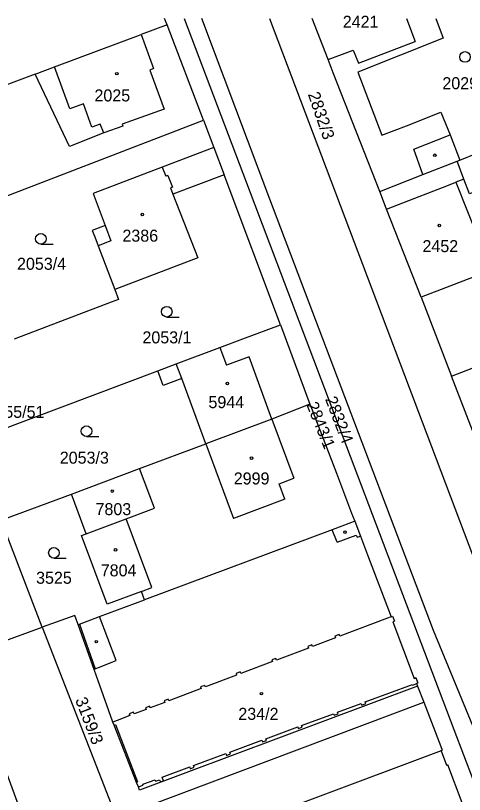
# Model space of a CAD drawing. Extents: x -564952 to -564307, y -1202373 to -1201847.
# Drawn here: x -564730.1 to -564666.6, y -1201959.8 to -1201849.7 of the extents above; entities that cross this region are included whole.
import ezdxf

# ---------------------------------------------------------------- set-up
doc = ezdxf.new("R2010")
doc.units = 0
for name, color, linetype in [('Hranice parcel', 7, 'Continuous'), ('Parcelní čísla', 7, 'Continuous'), ('Vnitřní kresba', 7, 'Continuous'), ('Značky budov', 7, 'Continuous'), ('Značky kultur', 7, 'Continuous')]:
    doc.layers.add(name, color=color, linetype=linetype)

msp = doc.modelspace()

# ---------------------------------------------------------------- linework, layer by layer
at = {"layer": 'Hranice parcel'}
for p, q in [((-564708.7, -1201850.95), (-564709.04, -1201850.07)), ((-564706.28, -1201850.07), (-564668.12, -1201950.64)), ((-564694.16, -1201875.63), (-564703.8, -1201850.07)), ((-564694.18, -1201850.07), (-564686.16, -1201871.23)), ((-564708.7, -1201850.95), (-564712.36, -1201852.32)), ((-564703.52, -1201864.46), (-564708.7, -1201850.95)), ((-564724.64, -1201856.92), (-564712.36, -1201852.32)), ((-564712.36, -1201852.32), (-564710.6, -1201857.14)), ((-564727.38, -1201857.94), (-564724.64, -1201856.92)), ((-564737.23, -1201877.39), (-564703.52, -1201864.46)), ((-564703.52, -1201864.46), (-564702.07, -1201868.33)), ((-564702.07, -1201868.33), (-564709.37, -1201871.11)), ((-564702.07, -1201868.33), (-564700.62, -1201872.17)), ((-564667.27, -1201870.1), (-564664.94, -1201869.19)), ((-564692.64, -1201893.4), (-564700.62, -1201872.17)), ((-564662.87, -1201885.69), (-564672.74, -1201889.5)), ((-564672.74, -1201889.5), (-564668.43, -1201900.65)), ((-564692.64, -1201893.4), (-564688.47, -1201904.65)), ((-564736.45, -1201909.86), (-564710.02, -1201899.92)), ((-564703.22, -1201910.26), (-564706.62, -1201900.99)), ((-564712.58, -1201913.74), (-564703.22, -1201910.26)), ((-564722.24, -1201917.34), (-564712.58, -1201913.74)), ((-564732.16, -1201921.04), (-564722.24, -1201917.34)), ((-564720.15, -1201922.96), (-564722.24, -1201917.34)), ((-564726.36, -1201936.19), (-564732.16, -1201921.04)), ((-564720.15, -1201922.96), (-564714.47, -1201920.84)), ((-564711.89, -1201932.3), (-564712.33, -1201931.11)), ((-564721.74, -1201934.52), (-564726.36, -1201936.19)), ((-564673.25, -1201944.51), (-564672.37, -1201946.79)), ((-564668.12, -1201950.64), (-564653.5, -1201989.14))]:
    msp.add_line(p, q, dxfattribs=at)
for points in [[(-564678.6, -1201874.56), (-564685.18, -1201857.76), (-564685.91, -1201855.87), (-564688.16, -1201850.07)], [(-564670.64, -1201850.07), (-564669.6, -1201852.87), (-564681.68, -1201857.67), (-564678.29, -1201866.56), (-564674.81, -1201865.25), (-564669.96, -1201863.32), (-564668.61, -1201866.52), (-564667.27, -1201870.1)], [(-564710.6, -1201857.14), (-564711.16, -1201857.36), (-564709.11, -1201862.88), (-564715.07, -1201865.02), (-564714.96, -1201865.29), (-564717.67, -1201866.26), (-564722.49, -1201868.17), (-564727.38, -1201857.94)], [(-564727.38, -1201857.94), (-564753.52, -1201867.7), (-564747.75, -1201881.47)], [(-564678.6, -1201874.56), (-564672.48, -1201872.15), (-564667.64, -1201870.24), (-564667.27, -1201870.1)], [(-564709.37, -1201871.11), (-564719.17, -1201874.83), (-564717.48, -1201879.35), (-564719.29, -1201880.05), (-564718.94, -1201880.95), (-564718.45, -1201882.23), (-564716.1, -1201888.41)], [(-564686.16, -1201871.23), (-564677.08, -1201895.29), (-564660.17, -1201939.88), (-564659.23, -1201942.17), (-564652.34, -1201954.8), (-564647.57, -1201960.74), (-564641.3, -1201967.43), (-564636.51, -1201971.74), (-564631.4, -1201974.9), (-564623.41, -1201978.76)], [(-564700.62, -1201872.17), (-564707.88, -1201874.94), (-564704.36, -1201883.94), (-564716.1, -1201888.41)], [(-564663.07, -1201873.83), (-564665.89, -1201874.89), (-564666.68, -1201872.79), (-564667.81, -1201873.23), (-564662.87, -1201885.69)], [(-564672.74, -1201889.5), (-564677.63, -1201877.03), (-564678.6, -1201874.56)], [(-564661.15, -1201960.44), (-564670.99, -1201936.66), (-564694.16, -1201875.63)], [(-564716.1, -1201888.41), (-564715.57, -1201889.81), (-564716.6, -1201890.2), (-564730.34, -1201895.42)], [(-564710.02, -1201899.92), (-564707.39, -1201898.93), (-564701.23, -1201896.62), (-564697.99, -1201895.41), (-564692.64, -1201893.4)], [(-564668.43, -1201900.65), (-564659.44, -1201897.19), (-564656.68, -1201896.09)], [(-564706.62, -1201900.99), (-564709.25, -1201901.97), (-564710.02, -1201899.92)], [(-564661.94, -1201917.34), (-564664.31, -1201911.26), (-564668.43, -1201900.65)], [(-564688.47, -1201904.65), (-564693.85, -1201906.77), (-564703.22, -1201910.26)], [(-564688.47, -1201904.65), (-564688.27, -1201905.18), (-564684.73, -1201914.39)], [(-564714.47, -1201920.84), (-564710.49, -1201919.36), (-564712.58, -1201913.74)], [(-564684.73, -1201914.39), (-564682.57, -1201920.04), (-564682.13, -1201921.2)], [(-564712.33, -1201931.11), (-564710.85, -1201930.56), (-564714.47, -1201920.84)], [(-564682.13, -1201921.2), (-564682.58, -1201921.37), (-564685.33, -1201922.39), (-564711.89, -1201932.3)], [(-564682.13, -1201921.2), (-564681.34, -1201923.29), (-564680.33, -1201925.94), (-564676.99, -1201934.7), (-564676.78, -1201934.62), (-564676.52, -1201935.32), (-564676.76, -1201935.41), (-564673.74, -1201943.42), (-564673.49, -1201943.32), (-564673.2, -1201944.1), (-564673.38, -1201944.17), (-564673.25, -1201944.51)], [(-564712.33, -1201931.11), (-564717.17, -1201932.91), (-564720.79, -1201923.2), (-564720.15, -1201922.96)], [(-564721.28, -1201935.81), (-564721.1, -1201935.74), (-564718.26, -1201934.68), (-564711.89, -1201932.3)], [(-564721.28, -1201935.81), (-564721.55, -1201935.06), (-564721.74, -1201934.52)], [(-564711.3, -1202011.73), (-564714.18, -1202003.86), (-564737.5, -1201940.24), (-564726.36, -1201936.19)], [(-564726.36, -1201936.19), (-564715.86, -1201963.16), (-564672.37, -1201946.79)], [(-564673.25, -1201944.51), (-564712.62, -1201959.24), (-564712.76, -1201958.76), (-564713.05, -1201958.13), (-564716.2, -1201950.04), (-564716.38, -1201949.6), (-564716.43, -1201949.46), (-564721.28, -1201935.81)], [(-564672.37, -1201946.79), (-564669.95, -1201953.07), (-564669.75, -1201953.6), (-564669.89, -1201953.65)], [(-564669.89, -1201953.65), (-564706.41, -1201967.36), (-564714.12, -1201970.26), (-564699.64, -1202009.87)], [(-564669.89, -1201953.65), (-564669.13, -1201955.68), (-564668.99, -1201955.63), (-564666.96, -1201960.96)]]:
    msp.add_lwpolyline(points, dxfattribs=at)
at = {"layer": 'Vnitřní kresba'}
for p, q in [((-564674.82, -1201850.07), (-564673.59, -1201853.3)), ((-564681.62, -1201856.39), (-564673.59, -1201853.3)), ((-564685.91, -1201855.87), (-564682.73, -1201854.69)), ((-564682.73, -1201854.69), (-564682.34, -1201854.54)), ((-564682.34, -1201854.54), (-564681.62, -1201856.39)), ((-564722.45, -1201862.85), (-564724.64, -1201856.92)), ((-564720.54, -1201862.14), (-564722.45, -1201862.85)), ((-564719.33, -1201865.46), (-564720.54, -1201862.14)), ((-564718.17, -1201865), (-564719.33, -1201865.46)), ((-564717.67, -1201866.26), (-564718.17, -1201865)), ((-564673.76, -1201868.54), (-564668.61, -1201866.52)), ((-564672.48, -1201872.15), (-564673.76, -1201868.54)), ((-564666.68, -1201872.79), (-564667.64, -1201870.24)), ((-564709.37, -1201871.11), (-564708.87, -1201872.38)), ((-564708.59, -1201872.27), (-564708.87, -1201872.38)), ((-564708.59, -1201872.27), (-564707.95, -1201873.91)), ((-564707.95, -1201873.91), (-564708.23, -1201874.02)), ((-564708.23, -1201874.02), (-564707.88, -1201874.94)), ((-564673.62, -1201875.48), (-564669.1, -1201873.73)), ((-564669.1, -1201873.73), (-564667.81, -1201873.23)), ((-564677.63, -1201877.03), (-564673.62, -1201875.48)), ((-564717.48, -1201879.35), (-564716.66, -1201881.54)), ((-564716.66, -1201881.54), (-564718.45, -1201882.23)), ((-564701.23, -1201896.62), (-564700.28, -1201899.11)), ((-564697.07, -1201897.94), (-564700.28, -1201899.11)), ((-564693.85, -1201906.77), (-564697.07, -1201897.94)), ((-564706.62, -1201900.99), (-564707.39, -1201898.93)), ((-564693.85, -1201906.77), (-564690.77, -1201915.12)), ((-564703.22, -1201910.26), (-564699.3, -1201920.79)), ((-564692.84, -1201915.88), (-564690.77, -1201915.12)), ((-564692.04, -1201918.06), (-564692.84, -1201915.88)), ((-564692.04, -1201918.06), (-564699.3, -1201920.79)), ((-564684.61, -1201924.17), (-564685.33, -1201922.39)), ((-564684.61, -1201924.17), (-564681.92, -1201923.16)), ((-564681.92, -1201923.16), (-564681.81, -1201923.46)), ((-564681.81, -1201923.46), (-564681.34, -1201923.29)), ((-564715.89, -1201940.91), (-564718.26, -1201934.68)), ((-564721.1, -1201935.74), (-564718.88, -1201942.05)), ((-564677.48, -1201934.89), (-564684.23, -1201937.44)), ((-564676.99, -1201934.7), (-564677.48, -1201934.89)), ((-564684.84, -1201937.67), (-564688.12, -1201938.91)), ((-564684.32, -1201937.2), (-564684.93, -1201937.43)), ((-564684.93, -1201937.43), (-564684.84, -1201937.67)), ((-564684.23, -1201937.44), (-564684.32, -1201937.2)), ((-564688.21, -1201938.67), (-564688.79, -1201938.89)), ((-564688.79, -1201938.89), (-564688.7, -1201939.13)), ((-564688.12, -1201938.91), (-564688.21, -1201938.67)), ((-564688.7, -1201939.13), (-564693.2, -1201940.83)), ((-564718.41, -1201941.87), (-564715.89, -1201940.91)), ((-564693.78, -1201941.05), (-564698.24, -1201942.74)), ((-564693.29, -1201940.6), (-564693.87, -1201940.82)), ((-564693.87, -1201940.82), (-564693.78, -1201941.05)), ((-564693.2, -1201940.83), (-564693.29, -1201940.6)), ((-564718.88, -1201942.05), (-564718.41, -1201941.87)), ((-564698.85, -1201942.97), (-564703.28, -1201944.64)), ((-564698.33, -1201942.5), (-564698.94, -1201942.73)), ((-564698.94, -1201942.73), (-564698.85, -1201942.97)), ((-564698.24, -1201942.74), (-564698.33, -1201942.5)), ((-564703.37, -1201944.41), (-564703.97, -1201944.64)), ((-564703.28, -1201944.64), (-564703.37, -1201944.41)), ((-564680.64, -1201946.75), (-564673.97, -1201944.28)), ((-564673.97, -1201944.28), (-564673.93, -1201944.37)), ((-564673.93, -1201944.37), (-564673.38, -1201944.17)), ((-564703.88, -1201944.87), (-564708.45, -1201946.6)), ((-564703.97, -1201944.64), (-564703.88, -1201944.87)), ((-564708.54, -1201946.37), (-564709.12, -1201946.59)), ((-564709.12, -1201946.59), (-564709.03, -1201946.82)), ((-564708.45, -1201946.6), (-564708.54, -1201946.37)), ((-564680.55, -1201946.98), (-564680.64, -1201946.75)), ((-564711.68, -1201947.82), (-564713.36, -1201948.46)), ((-564711.16, -1201947.36), (-564711.76, -1201947.59)), ((-564711.76, -1201947.59), (-564711.68, -1201947.82)), ((-564711.08, -1201947.59), (-564711.16, -1201947.36)), ((-564709.03, -1201946.82), (-564711.08, -1201947.59)), ((-564684.58, -1201948.21), (-564681.22, -1201946.97)), ((-564681.22, -1201946.97), (-564681.13, -1201947.2)), ((-564681.13, -1201947.2), (-564680.55, -1201946.98)), ((-564713.96, -1201948.69), (-564715.76, -1201949.37)), ((-564713.45, -1201948.22), (-564714.05, -1201948.45)), ((-564714.05, -1201948.45), (-564713.96, -1201948.69)), ((-564713.36, -1201948.46), (-564713.45, -1201948.22)), ((-564689.65, -1201950.09), (-564685.14, -1201948.42)), ((-564685.14, -1201948.42), (-564685.05, -1201948.65)), ((-564685.05, -1201948.65), (-564684.49, -1201948.44)), ((-564684.49, -1201948.44), (-564684.58, -1201948.21)), ((-564715.76, -1201949.37), (-564716.38, -1201949.6)), ((-564716.2, -1201950.04), (-564716.02, -1201949.97)), ((-564716.02, -1201949.97), (-564712.87, -1201958.06)), ((-564689.56, -1201950.32), (-564689.65, -1201950.09)), ((-564694.71, -1201951.96), (-564690.21, -1201950.3)), ((-564690.21, -1201950.3), (-564690.13, -1201950.53)), ((-564690.13, -1201950.53), (-564689.56, -1201950.32)), ((-564699.81, -1201953.85), (-564695.27, -1201952.17)), ((-564695.27, -1201952.17), (-564695.18, -1201952.41)), ((-564695.18, -1201952.41), (-564694.62, -1201952.2)), ((-564694.62, -1201952.2), (-564694.71, -1201951.96)), ((-564704.94, -1201955.75), (-564700.4, -1201954.07)), ((-564700.4, -1201954.07), (-564700.31, -1201954.31)), ((-564700.31, -1201954.31), (-564699.72, -1201954.09)), ((-564699.72, -1201954.09), (-564699.81, -1201953.85)), ((-564709.39, -1201957.41), (-564705.5, -1201955.96)), ((-564705.5, -1201955.96), (-564705.42, -1201956.2)), ((-564705.42, -1201956.2), (-564704.85, -1201955.99)), ((-564704.85, -1201955.99), (-564704.94, -1201955.75)), ((-564712.14, -1201958.41), (-564710.38, -1201957.77)), ((-564710.38, -1201957.77), (-564710.31, -1201957.97)), ((-564710.31, -1201957.97), (-564709.75, -1201957.76)), ((-564709.75, -1201957.76), (-564709.64, -1201958.07)), ((-564709.21, -1201957.91), (-564709.39, -1201957.41)), ((-564712.87, -1201958.06), (-564713.05, -1201958.13)), ((-564712.76, -1201958.76), (-564712.1, -1201958.52)), ((-564712.1, -1201958.52), (-564712.14, -1201958.41)), ((-564709.64, -1201958.07), (-564709.21, -1201957.91))]:
    msp.add_line(p, q, dxfattribs=at)
at = {"layer": 'Značky budov'}
for centre in [(-564715.81, -1201857.86), (-564670.8, -1201869.41), (-564712.21, -1201877.8), (-564670.16, -1201879.35), (-564700.16, -1201901.71), (-564696.74, -1201912.27), (-564716.46, -1201916.93), (-564683.52, -1201922.74), (-564715.99, -1201925.24), (-564718.72, -1201938.23), (-564695.34, -1201945.59)]:
    msp.add_circle(centre, 0.175, dxfattribs=at)
at = {"layer": 'Značky kultur'}
for p, q in [((-564726.57, -1201881.99), (-564724.82, -1201881.99)), ((-564708.74, -1201892.3), (-564706.99, -1201892.3)), ((-564720.1, -1201909.2), (-564718.35, -1201909.2)), ((-564724.72, -1201926.41), (-564722.97, -1201926.41))]:
    msp.add_line(p, q, dxfattribs=at)
for centre in [(-564666.53, -1201855.51), (-564726.57, -1201881.24), (-564708.74, -1201891.55), (-564720.1, -1201908.45), (-564724.72, -1201925.66)]:
    msp.add_circle(centre, 0.75, dxfattribs=at)

# ---------------------------------------------------------------- texts
at = {"layer": 'Parcelní čísla'}
for s, p in [('2421', (-564683.83, -1201851.38)), ('2029/2', (-564669.73, -1201860.07)), ('2025', (-564718.98, -1201861.8)), ('2386', (-564715.02, -1201881.64)), ('2452', (-564672.55, -1201883.12)), ('2053/4', (-564729.94, -1201885.62)), ('2053/1', (-564712.19, -1201896.03)), ('5944', (-564702.84, -1201905.19)), ('2055/51', (-564734.27, -1201906.57)), ('2053/3', (-564723.89, -1201913.05)), ('2999', (-564699.26, -1201915.99)), ('7803', (-564718.83, -1201920.33)), ('7804', (-564718.09, -1201928.99)), ('3525', (-564727.24, -1201930.04)), ('234/2', (-564698.61, -1201949.29))]:
    msp.add_text(s, height=1.7, dxfattribs=at).set_placement(p)
for s, rotation, p in [('2832/3', 289, (-564688.79, -1201860.78)), ('2832/4', 291, (-564686.36, -1201903.9)), ('2843/1', 292, (-564689.01, -1201904.7)), ('3159/3', 291, (-564721.73, -1201946.46))]:
    msp.add_text(s, height=1.7, rotation=rotation, dxfattribs=at).set_placement(p)

doc.saveas('drawing.dxf')
